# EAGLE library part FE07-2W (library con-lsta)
FEMALE HEADER
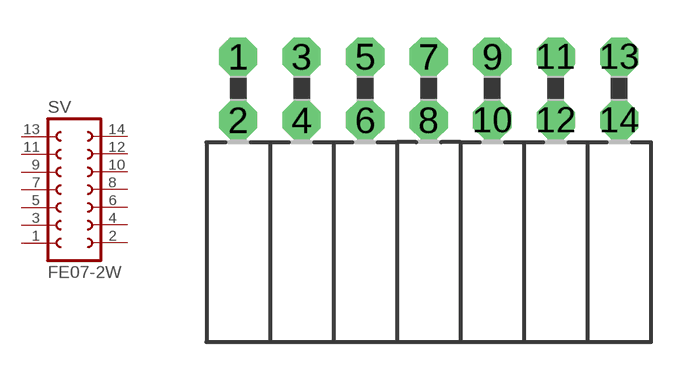
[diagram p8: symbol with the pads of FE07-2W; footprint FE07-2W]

Designator prefix SV

## FE07-2W (OC_FARNELL: unknown; OC_NEWARK: unknown)  [FE07-2W]
1  1  pas
2  2  pas
3  3  pas
4  4  pas
5  5  pas
6  6  pas
7  7  pas
8  8  pas
9  9  pas
10  10  pas
11  11  pas
12  12  pas
13  13  pas
14  14  pas

## Footprint FE07-2W (pad centres in mm)
FEMALE HEADER
drill 1.016 octagon: 1 -7.62,1.27; 2 -7.62,-1.27; 3 -5.08,1.27; 4 -5.08,-1.27; 5 -2.54,1.27; 6 -2.54,-1.27; 7 0,1.27; 8 0,-1.27; 9 2.54,1.27; 10 2.54,-1.27; 11 5.08,1.27; 12 5.08,-1.27; 13 7.62,1.27; 14 7.62,-1.27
